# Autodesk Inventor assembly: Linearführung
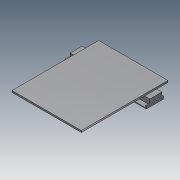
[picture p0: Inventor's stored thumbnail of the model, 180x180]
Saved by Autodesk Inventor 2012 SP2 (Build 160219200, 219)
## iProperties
Created: 2012-10
Part Number: Linearführung
Description: =<BEZEICHNUNG DEUTSCH>
Document SubType Name: Assembly
Designer: Massmann
Manufacturer: Standard
Standards Organization: Custom
Mass: 1611.82 g
Surface Area: 5742.58 cm^2
Volume: 594.768 cm^3
Density: 2.71 g/cm^3
Author: Massmann
IdentNr: =<SAP MATERIALNUMMER>
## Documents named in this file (3)
- C:\Local\PROFILE_Workspace\Inventor\Linearführung.iam
- C:\Local\PROFILE_Workspace\Inventor\Lineareinheit.iam
- C:\Local\PROFILE_Workspace\Inventor\Stelltisch.ipt
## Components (3 placed, 2 different names)
1. Lineareinheit:1 [sub-assembly] — Fluchtend:1, Passend:2, Fluchtend:3
2. Lineareinheit:2 [sub-assembly] — Fluchtend:1, Fluchtend:2, Passend:1, Passend:3, Fluchtend:3
3. Stelltisch:1 — Passend:1, Passend:2, Passend:3, Passend:4
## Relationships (7: Mate 4, Flush 3)
- Fluchtend:1 [Flush]: Lineareinheit:1 ↔ Lineareinheit:2
- Fluchtend:2 [Flush]: Lineareinheit:2
- Passend:1 [Mate]: Lineareinheit:2 ↔ Stelltisch:1
- Passend:2 [Mate]: Lineareinheit:1 ↔ Stelltisch:1
- Passend:3 [Mate]: Lineareinheit:2 ↔ Stelltisch:1
- Passend:4 [Mate]: Stelltisch:1
- Fluchtend:3 [Flush]: Lineareinheit:1 ↔ Lineareinheit:2
